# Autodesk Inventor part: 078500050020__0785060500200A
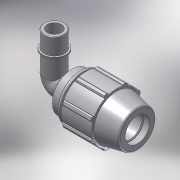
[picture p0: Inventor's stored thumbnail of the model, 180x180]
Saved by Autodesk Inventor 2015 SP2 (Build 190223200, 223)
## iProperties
Created: 2017-02
Part Number: 078500050020__0785060500200A
Material: PVC-Piping
Description: PLASSON 90° ELBOW MALE ADAPTOR 50-2"
Document SubType Name: Modeling
Designer: KIM
Mass: 92.6774 g
Surface Area: 199.44 cm^2
Volume: 66.1981 cm^3
Density: 1.4 g/cm^3
Appearance: Smooth - White
Author: KIM
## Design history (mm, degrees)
derived "07850.ipt"
feature "Solid1::07850.ipt"
tag "TaggingFeature1"
body "Solid1"
other parameters: "d4" = 12, "d5" = 36, "d7" = 96, "d9" = 20.57143, "d11" = 4.8, "d13" = 120 deg, "d15" = 12 deg, "d16" = 83.52, "d18" = 2.5, "d19" = 35 deg, "d20" = 17.5 deg, "d21" = 89.28, "d23" = 0, "d25" = 360 deg, "d27" = 1.92, "d33" = 1, "d42" = 53.28, "d43" = 2.88, "d46" = 1.5, "d51" = 144, "d68" = 4.8, "d72" = 76, "d73" = 59.614, "d74" = 26, "d75" = 68.5561, "d76" = 41.7298, "d77" = 28.6, "d79" = 23.8456, "d80" = 1.78842, "d83" = 0, "d84" = 0, "d91" = 72, "d93" = 93, "d94" = 59.614, "d95" = 41.7298, "d96" = 14.4, "d97" = 50 deg, "E_" = 96, "A_" = 144, "l_" = 93, "l_2" = 26, "A_1" = 76, "R_" = 59.614
